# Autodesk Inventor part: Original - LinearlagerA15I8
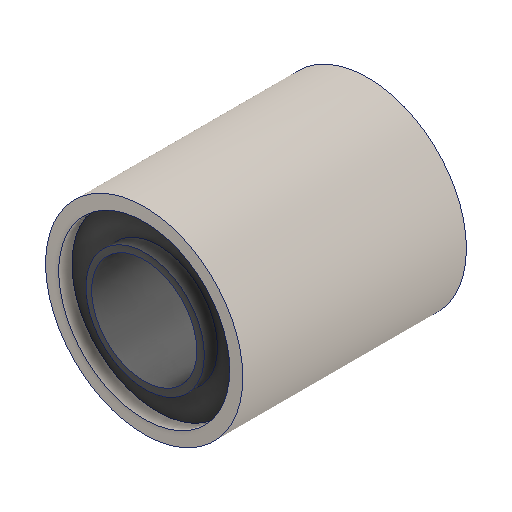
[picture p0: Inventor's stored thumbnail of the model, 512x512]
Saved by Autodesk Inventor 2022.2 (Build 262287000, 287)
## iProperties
Created: 2024-09
Part Number: Original - LinearlagerA15I8
Material: Generico
Document SubType Name: Modeling
Designer: 18907419
Density: 1 g/cm^3
Appearance: Default
Author: 18907419
Revision Number: ANY
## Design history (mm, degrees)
feature "Schnitt-Linear austragen3"
node "Solido1"
